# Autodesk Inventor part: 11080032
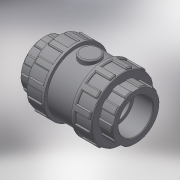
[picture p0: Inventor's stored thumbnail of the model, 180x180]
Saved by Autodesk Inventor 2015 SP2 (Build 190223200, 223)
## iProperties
Created: 2017-11
Part Number: 11080032
Material: Generic
Description: PLASSON CHECK VALVE CEM 32 PTFE COATED SPRING + EPDM O-RING
Document SubType Name: Modeling
Designer: KIM
Density: 1 g/cm^3
Appearance: Default
Author: KIM
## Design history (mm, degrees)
derived "110800 - 110600 110900-110000.ipt"
feature "Solid1::110800 - 110600 110900-110000.ipt"
tag "TaggingFeature1"
body "Solid1"
other parameters: "d0" = 102, "d1" = 32, "d2" = 66, "d3" = 22, "d4" = 25.6, "d5" = 15.4, "d7" = 44.8, "d8" = 59.4, "d13" = 0.96, "d23" = 22, "d24" = 63.36, "d25" = 0.64, "d26" = 0.96, "d27" = 9.9, "d28" = 4.95, "d29" = 16.5, "d30" = 0, "d35" = 0.96, "d39" = 33, "d45" = 360 deg, "d47" = 0.64, "d50" = 33, "d51" = 19.8, "d53" = 0, "d54" = 1.32, "d55" = 6.4, "d56" = 3.2, "d57" = 15.4, "d58" = 0, "d59" = 0.96, "d61" = 360 deg, "d_" = 32, "l_" = 22, "H_" = 102, "K_" = 66
